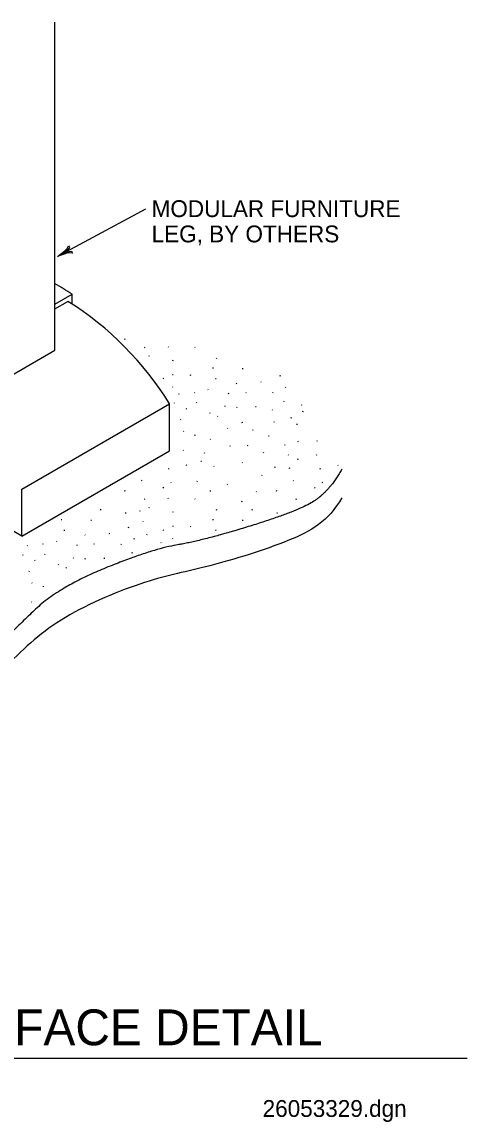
# Model space of a CAD drawing. Extents: x 10309.1 to 10402.7, y 9934 to 9975.2.
# Drawn here: x 10340.13 to 10355.99, y 9934.29 to 9973.46 of the extents above; entities that cross this region are included whole.
import ezdxf

# ---------------------------------------------------------------- set-up
doc = ezdxf.new("R2010")
doc.units = 0
for name, color, linetype in [('G-ANNO-TEXT', 7, 'Continuous'), ('G-DETL-OTLN', 7, 'Continuous'), ('G-DETL-PATT', 7, 'Continuous')]:
    doc.layers.add(name, color=color, linetype=linetype)

msp = doc.modelspace()

# ---------------------------------------------------------------- linework, layer by layer
at = {"layer": 'G-ANNO-TEXT'}
for p, q in [((10344.536, 9966.795), (10341.4, 9965.117)), ((10314.206, 9936.566), (10355.99, 9936.566))]:
    msp.add_line(p, q, dxfattribs=at)
msp.add_lwpolyline([(10341.466, 9965.153), (10341.739, 9965.278), (10341.814, 9965.296), (10341.898, 9965.299), (10341.934, 9965.233), (10341.824, 9965.238), (10341.724, 9965.227), (10341.633, 9965.199), (10341.525, 9965.163), (10341.4, 9965.117), (10341.507, 9965.196), (10341.597, 9965.265), (10341.671, 9965.326), (10341.736, 9965.403), (10341.792, 9965.497), (10341.828, 9965.431), (10341.779, 9965.363), (10341.722, 9965.311), (10341.466, 9965.153)], dxfattribs=at)
at = {"layer": 'G-DETL-OTLN'}
for p, q in [((10343.799, 9962.159), (10343.808, 9962.187)), ((10344.508, 9961.87), (10344.479, 9961.863)), ((10345.349, 9961.887), (10345.335, 9961.901)), ((10346.302, 9961.866), (10346.288, 9961.88)), ((10344.663, 9961.562), (10344.673, 9961.591)), ((10345.509, 9961.402), (10345.518, 9961.43)), ((10347.066, 9961.48), (10347.075, 9961.508)), ((10345.524, 9960.903), (10345.495, 9960.897)), ((10346.137, 9960.879), (10346.146, 9960.907)), ((10346.951, 9961.138), (10346.922, 9961.132)), ((10348.011, 9961.112), (10347.982, 9961.106)), ((10345.18, 9960.751), (10345.166, 9960.765)), ((10347.055, 9960.76), (10347.026, 9960.754)), ((10347.782, 9960.582), (10347.768, 9960.596)), ((10348.657, 9960.639), (10348.643, 9960.653)), ((10349.33, 9960.853), (10349.339, 9960.881)), ((10345.504, 9960.456), (10345.49, 9960.47)), ((10345.729, 9960.203), (10345.715, 9960.217)), ((10346.291, 9960.26), (10346.277, 9960.274)), ((10346.769, 9960.358), (10346.755, 9960.372)), ((10347.5, 9960.231), (10347.472, 9960.217)), ((10348.119, 9960.26), (10348.105, 9960.274)), ((10349.068, 9960.253), (10349.078, 9960.281)), ((10349.526, 9960.448), (10349.536, 9960.476)), ((10345.568, 9959.89), (10345.571, 9959.899)), ((10346.347, 9959.897), (10346.356, 9959.925)), ((10347.367, 9959.766), (10347.377, 9959.794)), ((10347.786, 9959.736), (10347.795, 9959.764)), ((10348.482, 9959.76), (10348.453, 9959.754)), ((10349.461, 9959.949), (10349.471, 9959.977)), ((10350.089, 9959.818), (10350.099, 9959.846)), ((10345.783, 9959.292), (10345.793, 9959.32)), ((10346.001, 9959.678), (10345.987, 9959.692)), ((10346.83, 9959.527), (10346.84, 9959.555)), ((10347.113, 9959.417), (10347.099, 9959.431)), ((10349.063, 9959.639), (10349.049, 9959.653)), ((10349.722, 9959.357), (10349.732, 9959.385)), ((10350.142, 9959.583), (10350.151, 9959.611)), ((10347.467, 9958.986), (10347.453, 9959)), ((10347.985, 9959.198), (10347.956, 9959.192)), ((10348.37, 9958.921), (10348.356, 9958.935)), ((10349.12, 9959.213), (10349.13, 9959.241)), ((10349.947, 9959.133), (10349.919, 9959.127)), ((10345.896, 9958.881), (10345.882, 9958.896)), ((10346.294, 9958.743), (10346.303, 9958.771)), ((10346.852, 9958.594), (10346.838, 9958.608)), ((10348.94, 9958.715), (10348.911, 9958.709)), ((10350.647, 9958.534), (10350.656, 9958.563)), ((10345.883, 9958.203), (10345.869, 9958.217)), ((10347.55, 9958.352), (10347.56, 9958.38)), ((10348.181, 9958.376), (10348.152, 9958.37)), ((10348.741, 9958.117), (10348.75, 9958.145)), ((10349.5, 9958.391), (10349.509, 9958.419)), ((10349.974, 9958.519), (10349.945, 9958.513)), ((10346.532, 9957.814), (10346.503, 9957.808)), ((10346.634, 9958.104), (10346.643, 9958.132)), ((10347.99, 9957.759), (10347.976, 9957.773)), ((10349.626, 9958.033), (10349.612, 9958.047)), ((10349.958, 9957.886), (10349.968, 9957.914)), ((10350.637, 9958.03), (10350.622, 9958.044)), ((10345.363, 9957.553), (10345.335, 9957.539)), ((10346.001, 9957.667), (10345.987, 9957.681)), ((10346.982, 9957.628), (10346.968, 9957.642)), ((10349.149, 9957.605), (10349.12, 9957.599)), ((10349.67, 9957.568), (10349.679, 9957.596)), ((10350.763, 9957.553), (10350.735, 9957.539)), ((10351.401, 9957.667), (10351.387, 9957.681)), ((10344.409, 9957.119), (10344.395, 9957.133)), ((10345.447, 9957.048), (10345.433, 9957.062)), ((10346.372, 9957.098), (10346.382, 9957.126)), ((10347.459, 9956.994), (10347.468, 9957.022)), ((10348.676, 9957.307), (10348.685, 9957.335)), ((10349.809, 9957.119), (10349.795, 9957.133)), ((10350.847, 9957.048), (10350.833, 9957.062)), ((10343.799, 9956.759), (10343.808, 9956.787)), ((10345.18, 9956.88), (10345.152, 9956.866)), ((10346.859, 9956.757), (10346.83, 9956.751)), ((10348.487, 9956.727), (10348.473, 9956.741)), ((10349.199, 9956.759), (10349.208, 9956.787)), ((10350.58, 9956.88), (10350.552, 9956.866)), ((10344.508, 9956.47), (10344.479, 9956.463)), ((10344.663, 9956.162), (10344.673, 9956.191)), ((10345.349, 9956.487), (10345.335, 9956.501)), ((10346.302, 9956.466), (10346.288, 9956.48)), ((10347.969, 9956.38), (10347.978, 9956.408)), ((10349.908, 9956.47), (10349.879, 9956.463)), ((10342.935, 9956.08), (10342.945, 9956.108)), ((10343.841, 9955.973), (10343.812, 9955.967)), ((10344.336, 9956.041), (10344.345, 9956.069)), ((10345.509, 9956.002), (10345.518, 9956.03)), ((10347.066, 9956.08), (10347.075, 9956.108)), ((10348.335, 9956.08), (10348.345, 9956.108)), ((10349.241, 9955.973), (10349.212, 9955.967)), ((10341.551, 9955.738), (10341.522, 9955.732)), ((10342.611, 9955.712), (10342.582, 9955.706)), ((10343.93, 9955.453), (10343.939, 9955.481)), ((10344.448, 9955.657), (10344.434, 9955.671)), ((10345.524, 9955.503), (10345.495, 9955.497)), ((10346.137, 9955.479), (10346.146, 9955.507)), ((10346.951, 9955.738), (10346.922, 9955.732)), ((10348.011, 9955.712), (10347.982, 9955.706)), ((10341.655, 9955.36), (10341.626, 9955.354)), ((10342.382, 9955.182), (10342.368, 9955.196)), ((10343.257, 9955.239), (10343.243, 9955.253)), ((10344.126, 9955.048), (10344.136, 9955.076)), ((10344.585, 9955.196), (10344.594, 9955.224)), ((10345.18, 9955.351), (10345.166, 9955.365)), ((10345.504, 9955.056), (10345.49, 9955.07)), ((10347.055, 9955.36), (10347.026, 9955.354)), ((10340.329, 9954.803), (10340.315, 9954.817)), ((10340.891, 9954.86), (10340.877, 9954.874)), ((10341.369, 9954.958), (10341.355, 9954.972)), ((10342.1, 9954.831), (10342.072, 9954.817)), ((10342.719, 9954.86), (10342.705, 9954.874)), ((10343.668, 9954.853), (10343.678, 9954.881)), ((10344.859, 9954.663), (10344.864, 9954.66)), ((10345.096, 9954.916), (10345.082, 9954.93)), ((10340.162, 9954.471), (10340.171, 9954.499)), ((10340.601, 9954.278), (10340.587, 9954.292)), ((10340.947, 9954.497), (10340.956, 9954.525)), ((10341.967, 9954.366), (10341.977, 9954.394)), ((10342.386, 9954.336), (10342.395, 9954.364)), ((10343.082, 9954.36), (10343.053, 9954.354)), ((10344.061, 9954.549), (10344.071, 9954.577)), ((10340.383, 9953.892), (10340.393, 9953.92)), ((10341.43, 9954.127), (10341.44, 9954.155)), ((10341.713, 9954.017), (10341.699, 9954.031)), ((10340.496, 9953.481), (10340.482, 9953.496)), ((10340.894, 9953.343), (10340.903, 9953.371)), ((10341.452, 9953.194), (10341.438, 9953.208)), ((10340.483, 9952.803), (10340.469, 9952.817))]:
    msp.add_line(p, q, dxfattribs=at)
at = {"layer": 'G-DETL-PATT'}
for p, q in [((10341.3, 9961.771), (10341.3, 9973.464)), ((10341.3, 9963.416), (10341.916, 9963.772)), ((10341.916, 9963.422), (10341.916, 9963.772)), ((10341.3, 9963.244), (10341.77, 9963.515)), ((10337.606, 9959.639), (10341.3, 9961.771)), ((10340.13, 9955.152), (10330.777, 9960.552)), ((10340.13, 9956.826), (10345.392, 9959.864)), ((10345.392, 9958.19), (10345.392, 9959.864)), ((10340.13, 9955.152), (10345.392, 9958.19)), ((10340.13, 9955.152), (10340.13, 9956.826))]:
    msp.add_line(p, q, dxfattribs=at)
for centre, start, end in [((10335.725, 9954.197), 57.1162, 60.7338), ((10335.694, 9953.867), 31.7321, 57.7989)]:
    msp.add_arc(centre, 11.402, start, end, dxfattribs=at)
for points, degree in [([(10351.533, 9957.535), (10351.046, 9956.691), (10349.849, 9956.001), (10346.596, 9954.997), (10344.745, 9954.688), (10341.412, 9953.326), (10339.684, 9951.655), (10337.339, 9949.364), (10335.735, 9948.002), (10332.773, 9946.207), (10331.107, 9945.526), (10328.823, 9945.155), (10325.676, 9945.65), (10323.146, 9946.703), (10321.171, 9948.25), (10318.826, 9951.716), (10318.209, 9954.44), (10318.826, 9956.73), (10319.629, 9958.773), (10319.752, 9960.321), (10319.505, 9961.559), (10319.011, 9962.487)], 2), ([(10351.533, 9956.523), (10351.046, 9955.679), (10349.849, 9954.988), (10346.596, 9953.985), (10344.745, 9953.675), (10341.412, 9952.313), (10339.684, 9950.642), (10337.339, 9948.352), (10335.735, 9946.99), (10332.773, 9945.195), (10331.107, 9944.514), (10328.823, 9944.143), (10325.676, 9944.638), (10323.146, 9945.69), (10321.171, 9947.238), (10318.826, 9950.704), (10318.372, 9952.709), (10318.424, 9953.701), (10318.44, 9953.87)], 3)]:
    msp.add_open_spline(points, degree=degree, dxfattribs=at)

# ---------------------------------------------------------------- texts
at = {"layer": 'G-ANNO-TEXT'}
for s, height, p in [('MODULAR FURNITURE', 0.6, (10344.75, 9966.516)), ('LEG, BY OTHERS', 0.6, (10344.75, 9965.616)), ('POWER/FURNITURE INTERFACE DETAIL', 1.275, (10317.5, 9937.022)), ('26053329.dgn', 0.6, (10348.707, 9934.469))]:
    msp.add_text(s, height=height, dxfattribs=at).set_placement(p)

doc.saveas('drawing.dxf')
